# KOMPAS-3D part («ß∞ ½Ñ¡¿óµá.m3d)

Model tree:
1. Эскиз:1
2. Операция выдавливания:1
     Расстояние 1 = 5; Расстояние 2 = 1
3. Эскиз:2
4. Операция выдавливания:2
     Расстояние 1 = 2; Расстояние 2 = 1
5. Эскиз:3
6. Операция выдавливания:3
     Расстояние 1 = 18.5; Расстояние 2 = 1
7. Скругление:2
     Радиус = 0.1
8. Условное изображение резьбы:2
     Длина резьбы = 3; Шаг резьбы = 1.5; Номинальный диаметр резьбы = 5
9. Условное изображение резьбы:3
     Длина резьбы = 4.9; Шаг резьбы = 1.5; Номинальный диаметр резьбы = 4
10. Скругление:3
     Радиус = 0.1
